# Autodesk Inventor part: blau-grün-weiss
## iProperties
Created: 2004-10
Part Number: blau-grün-weiss
Document SubType Name: Modeling
Designer: sahrens
Manufacturer: Standard
Standards Organization: Custom
Author: sahrens
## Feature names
1. Extrusion1
2. Rundung2 [Fillet]
